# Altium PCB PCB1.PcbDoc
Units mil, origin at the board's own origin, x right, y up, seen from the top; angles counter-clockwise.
Board outline 6095 x 3360 mil, 2 copper layers (Top Layer, Bottom Layer); 128 components, 157 nets, 524 pads, 0 vias.
Unrouted connection lines stored in the file: 80.
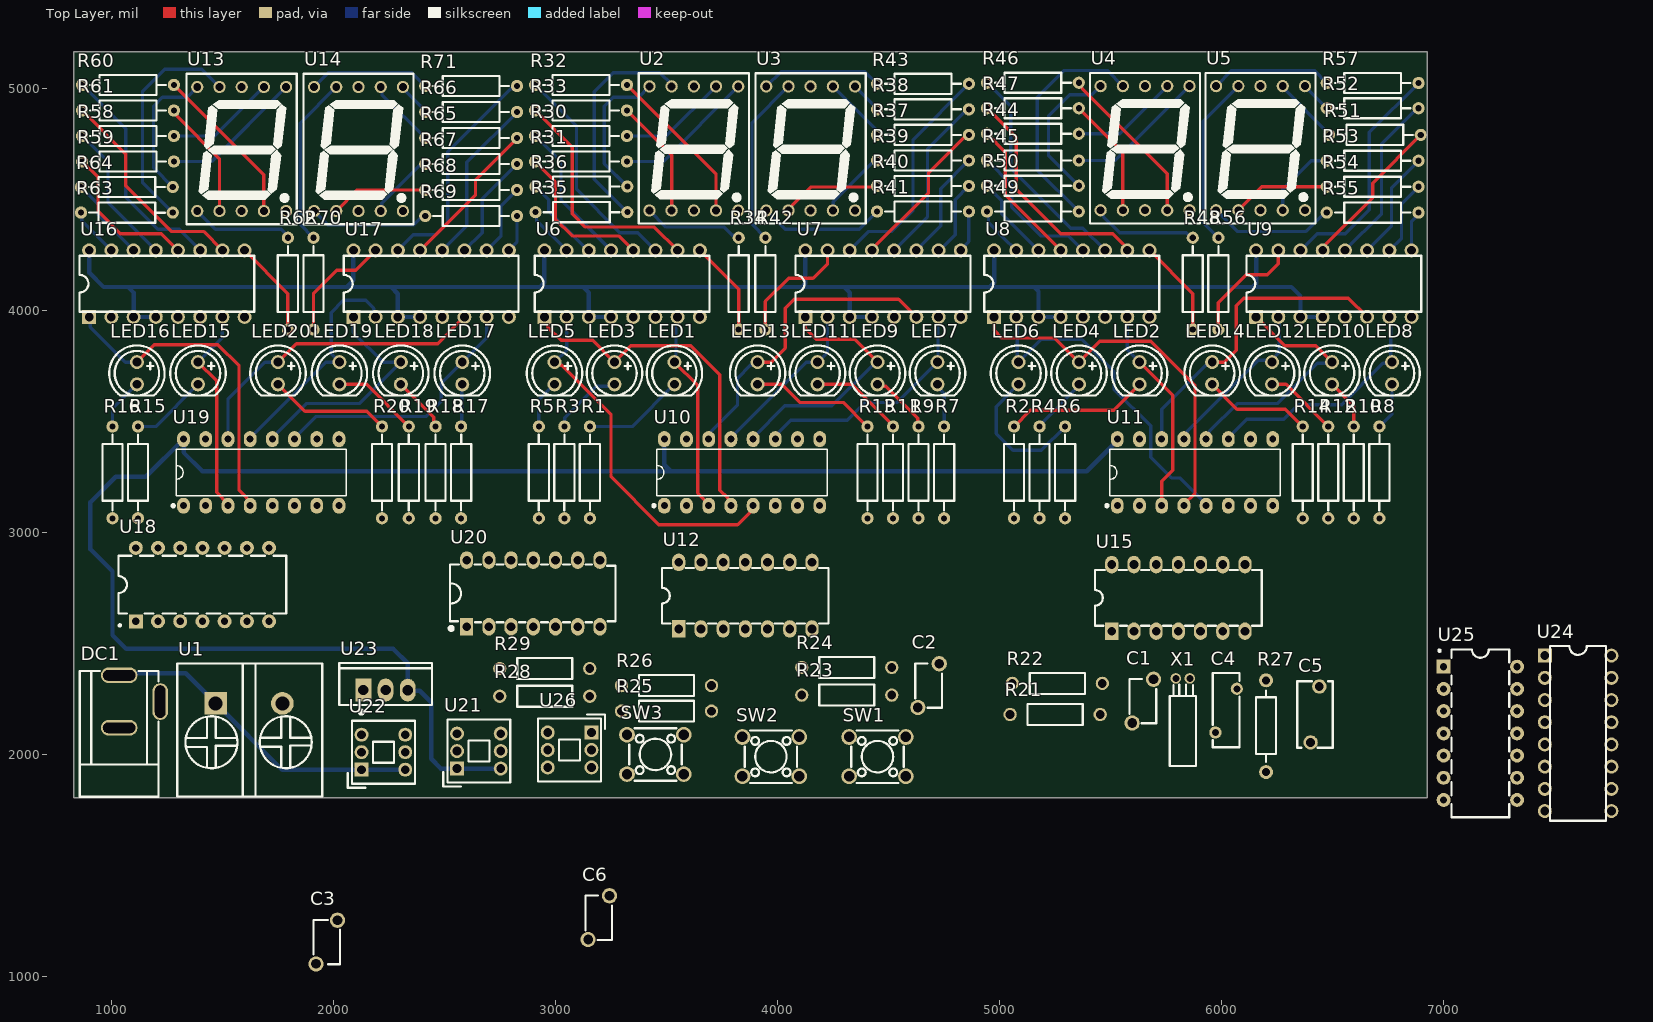
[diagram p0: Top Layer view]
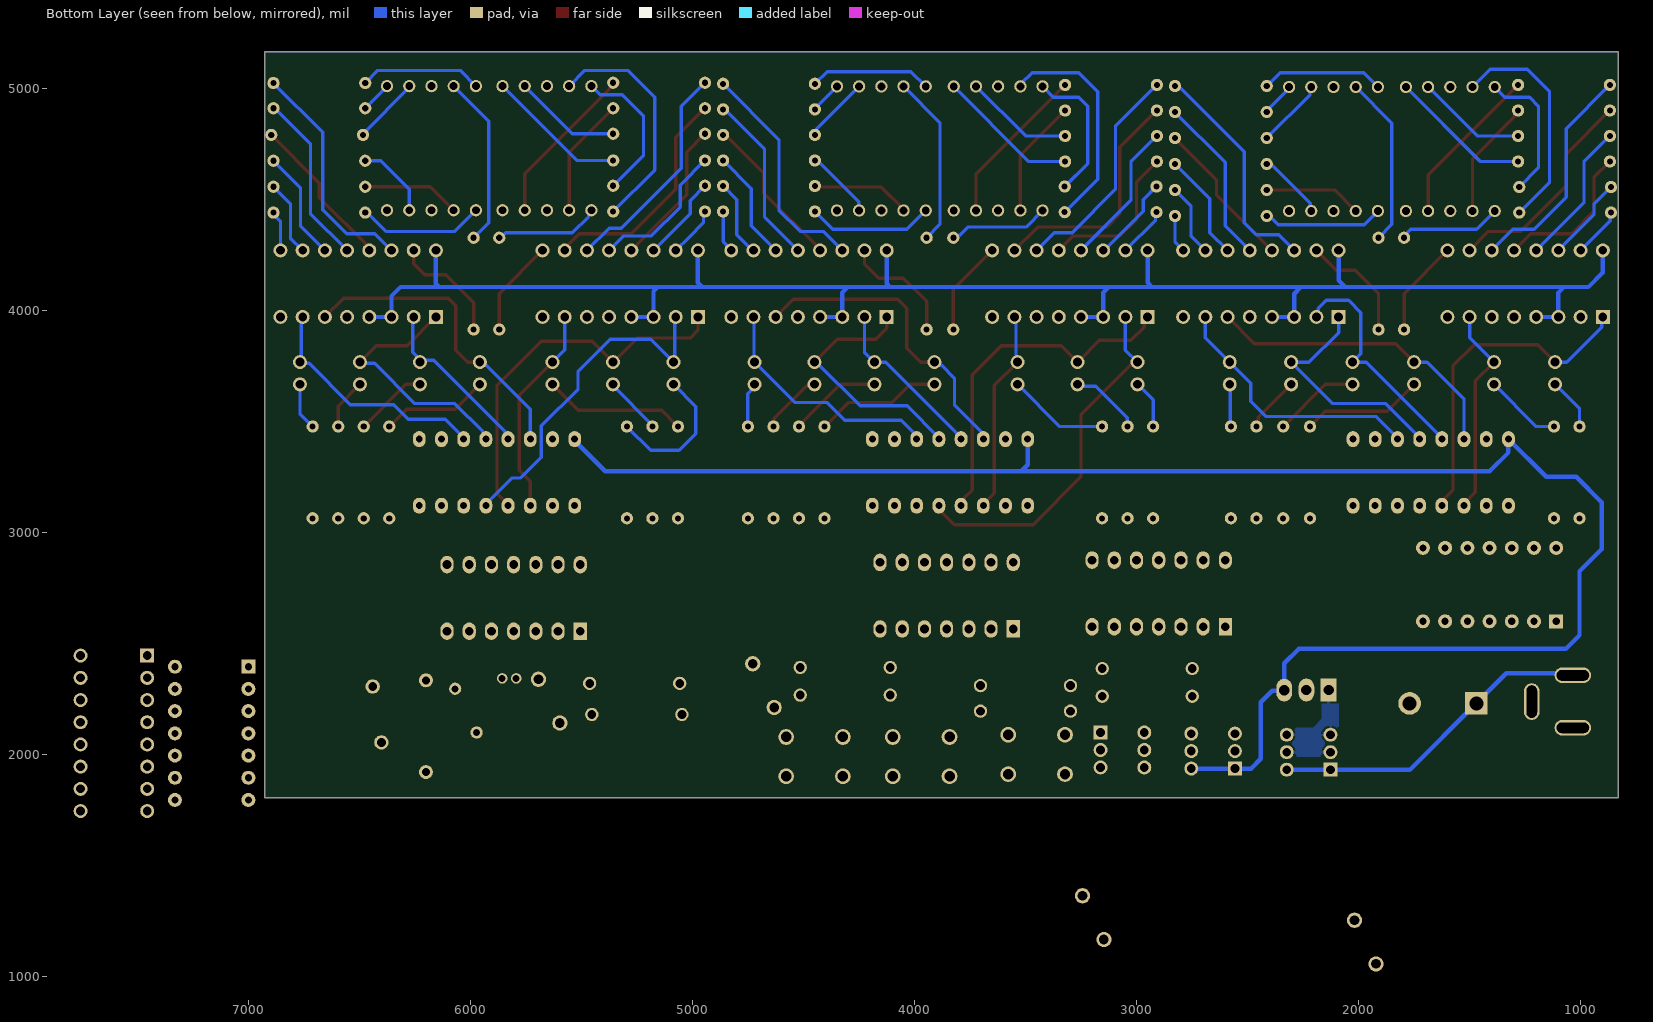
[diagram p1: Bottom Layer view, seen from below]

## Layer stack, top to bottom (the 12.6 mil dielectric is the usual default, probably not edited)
Top Solder: solder mask 0.4, Solder Resist, Dk 3.5
Top Layer: signal copper 1.4
Dielectric 1: dielectric 12.6, FR-4, Dk 4.8
Bottom Layer: signal copper 1.4
Bottom Solder: solder mask 0.4, Solder Resist, Dk 3.5

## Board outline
830,1805 6925,1805 6925,5165 830,5165

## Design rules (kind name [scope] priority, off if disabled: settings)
Clearance [All] p1: gap=10 ignorepadtopadclearanceinfootprint=FALSE
PolygonConnect [All] p1: connectstyle=Relief reliefconductorwidth=10 reliefentries=4 polygonreliefangle="90 Angle" airgapwidth=10
RoutingVias [All] p1: holewidth=28 width=50 viastyle="Through Hole" minholewidth=28 minwidth=50 maxholewidth=28 maxwidth=50
SolderMaskExpansion [All] p1: expansion=4 istentingtop=FALSE
SupplyNets "Schematic Supply Nets_3" [InNet('GND')] p1: voltage=0.000
SupplyNets "Schematic Supply Nets_1" [InNet('+D5V')] p2: voltage=0.000
SupplyNets "Schematic Supply Nets" [InNet('+5')] p3: voltage=0.000
Width [All] p1: maxlimit=50 minlimit=10 preferedwidth=15 minimp=50.000000 maximp=50.000000 favimp=50.000000
30 further rules are at their usual default settings.

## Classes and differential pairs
component class Display_SEC_MIN: LED1 LED2 LED3 LED4 LED5 LED6 LED7 LED8 LED9 LED10 LED11 LED12 LED13 LED14 R1 R2 R3 R4 R5 R6 R7 R8 R9 R10 R11 R12 R13 R14 R30 R31 R32 R33 R34 R35 R36 R37 R38 R39 R40 R41 R42 R43 R44 R45 R46 R47 R48 R49 R50 R51 R52 R53 R54 R55 R56 R57 U2 U3 U4 U5 U6 U7 U8 U9 U10 U11
component class Display_Hour: LED15 LED16 LED17 LED18 LED19 LED20 R15 R16 R17 R18 R19 R20 R58 R59 R60 R61 R62 R63 R64 R65 R66 R67 R68 R69 R70 R71 U12 U13 U14 U15 U16 U17 U18 U19 U20
component class CLK_SW: C1 C2 C3 C4 C5 C6 DC1 R21 R22 R23 R24 R25 R26 R27 R28 R29 SW1 SW2 SW3 U1 U21 U22 U23 U24 U25 U26 X1

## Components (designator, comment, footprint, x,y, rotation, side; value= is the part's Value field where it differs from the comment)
C1 "100pF" CAP-TH_L5.0-W3.0-P5.00-D0.6-S2.45 5645,2240 r90 top
C2 "100pF" CAP-TH_L5.0-W3.0-P5.00-D0.6-S2.45 4680,2310 r90 top
C3 "100pF" CAP-TH_L5.0-W3.0-P5.00-D0.6-S2.45 1970,1155 r270 top
C4 "560pF" CAP-TH_L8.5-W3.0-P5.00-D0.6-S2.5 6020,2197.19 r90 top
C5 "22pF" CAP-TH_L7.4-W4.0-P6.40-D0.5-S1.00 6420,2180 r90 top
C6 "100pF" CAP-TH_L5.0-W3.0-P5.00-D0.6-S2.45 3195,1265 r90 top
DC1 "DC-005-2.5A-2.0" CONN-TH_DC-005-2.5A-2.0 1127.53,2238.1 r90 top
LED1 "WP7113ID" LED-TH_BD5.0-P2.54-FD 3535.52,3716.7 r270 top locked
LED2 "WP7113ID" LED-TH_BD5.0-P2.54-FD 5630,3716.7 r270 top locked
LED3 "WP7113ID" LED-TH_BD5.0-P2.54-FD 3265.52,3716.7 r270 top locked
LED4 "WP7113ID" LED-TH_BD5.0-P2.54-FD 5357.5,3716.7 r270 top locked
LED5 "WP7113ID" LED-TH_BD5.0-P2.54-FD 2995.52,3716.7 r270 top locked
LED6 "WP7113ID" LED-TH_BD5.0-P2.54-FD 5085,3716.7 r270 top locked
LED7 "WP7113ID" LED-TH_BD5.0-P2.54-FD 4720.21,3716.7 r270 top locked
LED8 "WP7113ID" LED-TH_BD5.0-P2.54-FD 6767.15,3716.7 r270 top locked
LED9 "WP7113ID" LED-TH_BD5.0-P2.54-FD 4450.21,3716.7 r270 top locked
LED10 "WP7113ID" LED-TH_BD5.0-P2.54-FD 6497.15,3716.7 r270 top locked
LED11 "WP7113ID" LED-TH_BD5.0-P2.54-FD 4180.21,3716.7 r270 top locked
LED12 "WP7113ID" LED-TH_BD5.0-P2.54-FD 6227.15,3716.7 r270 top locked
LED13 "WP7113ID" LED-TH_BD5.0-P2.54-FD 3910.21,3716.7 r270 top locked
LED14 "WP7113ID" LED-TH_BD5.0-P2.54-FD 5957.15,3716.7 r270 top locked
LED15 "WP7113ID" LED-TH_BD5.0-P2.54-FD 1390,3716.7 r270 top locked
LED16 "WP7113ID" LED-TH_BD5.0-P2.54-FD 1115,3716.7 r270 top locked
LED17 "WP7113ID" LED-TH_BD5.0-P2.54-FD 2580.21,3716.7 r270 top locked
LED18 "WP7113ID" LED-TH_BD5.0-P2.54-FD 2303.55,3716.7 r270 top locked
LED19 "WP7113ID" LED-TH_BD5.0-P2.54-FD 2026.88,3716.7 r270 top locked
LED20 "WP7113ID" LED-TH_BD5.0-P2.54-FD 1750.21,3716.7 r270 top locked
R1 "330Ω" RES-TH_BD2.3-L6.5-P10.50-D0.5 3155,3270 r270 top locked
R2 "330Ω" RES-TH_BD2.3-L6.5-P10.50-D0.5 5065,3270 r270 top locked
R3 "330Ω" RES-TH_BD2.3-L6.5-P10.50-D0.5 3040,3270 r270 top locked
R4 "330Ω" RES-TH_BD2.3-L6.5-P10.50-D0.5 5180,3270 r270 top locked
R5 "330Ω" RES-TH_BD2.3-L6.5-P10.50-D0.5 2925,3270 r270 top locked
R6 "330Ω" RES-TH_BD2.3-L6.5-P10.50-D0.5 5295,3270 r270 top locked
R7 "330Ω" RES-TH_BD2.3-L6.5-P10.50-D0.5 4750,3270 r90 top locked
R8 "330Ω" RES-TH_BD2.3-L6.5-P10.50-D0.5 6710,3270 r90 top locked
R9 "330Ω" RES-TH_BD2.3-L6.5-P10.50-D0.5 4635,3270 r90 top locked
R10 "330Ω" RES-TH_BD2.3-L6.5-P10.50-D0.5 6595,3270 r90 top locked
R11 "330Ω" RES-TH_BD2.3-L6.5-P10.50-D0.5 4520,3270 r90 top locked
R12 "330Ω" RES-TH_BD2.3-L6.5-P10.50-D0.5 6480,3270 r90 top locked
R13 "330Ω" RES-TH_BD2.3-L6.5-P10.50-D0.5 4405,3270 r90 top locked
R14 "330Ω" RES-TH_BD2.3-L6.5-P10.50-D0.5 6365,3270 r90 top locked
R15 "330Ω" RES-TH_BD2.3-L6.5-P10.50-D0.5 1120,3270 r270 top locked
R16 "330Ω" RES-TH_BD2.3-L6.5-P10.50-D0.5 1005,3270 r270 top locked
R17 "330Ω" RES-TH_BD2.3-L6.5-P10.50-D0.5 2575,3270 r90 top locked
R18 "330Ω" RES-TH_BD2.3-L6.5-P10.50-D0.5 2460.04,3270 r90 top locked
R19 "330Ω" RES-TH_BD2.3-L6.5-P10.50-D0.5 2339.48,3270 r90 top locked
R20 "330Ω" RES-TH_BD2.3-L6.5-P10.50-D0.5 2218.93,3270 r90 top locked
R21 "10kΩ" RES-TH_BD2.4-L6.3-P10.30-D0.6 5250,2180 r180 top
R22 "10kΩ" RES-TH_BD2.4-L6.3-P10.30-D0.6 5260,2320 r180 top
R23 "10kΩ" RES-TH_BD2.4-L6.3-P10.30-D0.6 4311.76,2267.24 r180 top
R24 "10kΩ" RES-TH_BD2.4-L6.3-P10.30-D0.6 4311.76,2391.73 r180 top
R25 "10kΩ" RES-TH_BD2.4-L6.3-P10.30-D0.6 3500,2195 r0 top
R26 "10kΩ" RES-TH_BD2.4-L6.3-P10.30-D0.6 3500,2310 r180 top
R27 "10MΩ" RES-TH_BD2.2-L6.5-P10.50-D0.6 6200,2127.19 r90 top
R28 "10kΩ" RES-TH_BD2.4-L6.3-P10.30-D0.6 2951.76,2262.24 r180 top
R29 "10kΩ" RES-TH_BD2.4-L6.3-P10.30-D0.6 2951.76,2386.73 r0 top
R30 "330Ω" RES-TH_BD2.3-L6.5-P10.50-D0.5 3115,4785 r0 top locked
R31 "330Ω" RES-TH_BD2.3-L6.5-P10.50-D0.5 3115,4670 r0 top locked
R32 "330Ω" RES-TH_BD2.3-L6.5-P10.50-D0.5 3115,5015 r0 top locked
R33 "330Ω" RES-TH_BD2.3-L6.5-P10.50-D0.5 3115,4900 r0 top locked
R34 "330Ω" RES-TH_BD2.3-L6.5-P10.50-D0.5 3825,4120 r90 top locked
R35 "330Ω" RES-TH_BD2.3-L6.5-P10.50-D0.5 3116.75,4441.96 r0 top locked
R36 "330Ω" RES-TH_BD2.3-L6.5-P10.50-D0.5 3116.75,4557.57 r0 top locked
R37 "330Ω" RES-TH_BD2.3-L6.5-P10.50-D0.5 4655,4790 r180 top locked
R38 "330Ω" RES-TH_BD2.3-L6.5-P10.50-D0.5 4655,4905 r180 top locked
R39 "330Ω" RES-TH_BD2.3-L6.5-P10.50-D0.5 4655,4675 r180 top locked
R40 "330Ω" RES-TH_BD2.3-L6.5-P10.50-D0.5 4655,4560 r180 top locked
R41 "330Ω" RES-TH_BD2.3-L6.5-P10.50-D0.5 4655,4445 r180 top locked
R42 "330Ω" RES-TH_BD2.3-L6.5-P10.50-D0.5 3945,4120 r90 top locked
R43 "330Ω" RES-TH_BD2.3-L6.5-P10.50-D0.5 4655,5020 r180 top locked
R44 "330Ω" RES-TH_BD2.3-L6.5-P10.50-D0.5 5150,4795 r0 top locked
R45 "330Ω" RES-TH_BD2.3-L6.5-P10.50-D0.5 5150,4675 r0 top locked
R46 "330Ω" RES-TH_BD2.3-L6.5-P10.50-D0.5 5150,5025 r0 top locked
R47 "330Ω" RES-TH_BD2.3-L6.5-P10.50-D0.5 5150,4910 r0 top locked
R48 "330Ω" RES-TH_BD2.3-L6.5-P10.50-D0.5 5870,4120 r90 top locked
R49 "330Ω" RES-TH_BD2.3-L6.5-P10.50-D0.5 5150,4445 r0 top locked
R50 "330Ω" RES-TH_BD2.3-L6.5-P10.50-D0.5 5150,4560.83 r0 top locked
R51 "330Ω" RES-TH_BD2.3-L6.5-P10.50-D0.5 6690,4790 r180 top locked
R52 "330Ω" RES-TH_BD2.3-L6.5-P10.50-D0.5 6680,4910 r180 top locked
R53 "330Ω" RES-TH_BD2.3-L6.5-P10.50-D0.5 6680,4673.33 r180 top locked
R54 "330Ω" RES-TH_BD2.3-L6.5-P10.50-D0.5 6680,4556.67 r180 top locked
R55 "330Ω" RES-TH_BD2.3-L6.5-P10.50-D0.5 6680,4440 r180 top locked
R56 "330Ω" RES-TH_BD2.3-L6.5-P10.50-D0.5 5985,4120 r90 top locked
R57 "330Ω" RES-TH_BD2.3-L6.5-P10.50-D0.5 6680,5023.33 r180 top locked
R58 "330Ω" RES-TH_BD2.3-L6.5-P10.50-D0.5 1075,4785 r0 top locked
R59 "330Ω" RES-TH_BD2.3-L6.5-P10.50-D0.5 1075,4670 r0 top locked
R60 "330Ω" RES-TH_BD2.3-L6.5-P10.50-D0.5 1075,5015 r0 top locked
R61 "330Ω" RES-TH_BD2.3-L6.5-P10.50-D0.5 1075,4900 r0 top locked
R62 "330Ω" RES-TH_BD2.3-L6.5-P10.50-D0.5 1795,4120 r90 top locked
R63 "330Ω" RES-TH_BD2.3-L6.5-P10.50-D0.5 1070,4440 r0 top locked
R64 "330Ω" RES-TH_BD2.3-L6.5-P10.50-D0.5 1070,4555 r0 top locked
R65 "330Ω" RES-TH_BD2.3-L6.5-P10.50-D0.5 2620,4776 r180 top locked
R66 "330Ω" RES-TH_BD2.3-L6.5-P10.50-D0.5 2620,4893 r180 top locked
R67 "330Ω" RES-TH_BD2.3-L6.5-P10.50-D0.5 2620,4659 r180 top locked
R68 "330Ω" RES-TH_BD2.3-L6.5-P10.50-D0.5 2620,4542 r180 top locked
R69 "330Ω" RES-TH_BD2.3-L6.5-P10.50-D0.5 2620,4425 r180 top locked
R70 "330Ω" RES-TH_BD2.3-L6.5-P10.50-D0.5 1910,4120 r90 top locked
R71 "330Ω" RES-TH_BD2.3-L6.5-P10.50-D0.5 2620,5010 r180 top locked
SW1 "TS665CJ" SW-TH_4P-L6.0-W6.0-P4.50-LS6.5 4450,1990 r180 top
SW2 "TS665CJ" SW-TH_4P-L6.0-W6.0-P4.50-LS6.5 3970,1990 r180 top
SW3 "TS665CJ" SW-TH_4P-L6.0-W6.0-P4.50-LS6.5 3450,2000 r0 top
U1 "DBT50G-7.62-2P" CONN-TH_2P-P7.62_L15.2-W16.7-EX4.2 1620,2230 r0 top
U2 "HDSP-5501" LED-SEG-TH_HDSP-A 3623.03,4729.02 r0 top locked
U3 "HDSP-5501" LED-SEG-TH_HDSP-A 4149.09,4729.02 r0 top locked
U4 "HDSP-5501" LED-SEG-TH_HDSP-A 5655,4730 r0 top locked
U5 "HDSP-5501" LED-SEG-TH_HDSP-A 6175,4730 r0 top locked
U6 "CD4511BE" DIP-16_L19.8-W6.5-P2.54-LS7.6-BL 3300,4120 r0 top locked
U7 "CD4511BE" DIP-16_L19.8-W6.5-P2.54-LS7.6-BL 4475.01,4120 r0 top locked
U8 "CD4511BE" DIP-16_L19.8-W6.5-P2.54-LS7.6-BL 5325.01,4120 r0 top locked
U9 "CD4511BE" DIP-16_L19.8-W6.5-P2.54-LS7.6-BL 6505.01,4120 r0 top locked
U10 "CD4518BE" DIP-16_L19.3-W6.4-P2.54-LS7.6-BL 3840,3270 r0 top locked
U11 "CD4518BE" DIP-16_L19.3-W6.4-P2.54-LS7.6-BL 5880,3270 r0 top locked
U12 "CD4081BE" PDIP-14_L19.3-W6.4-P2.54-LS7.6-BL 3855,2715 r0 top
U13 "HDSP-5501" LED-SEG-TH_HDSP-A 1586.86,4726.42 r0 top locked
U14 "HDSP-5501" LED-SEG-TH_HDSP-A 2112.92,4726.42 r0 top locked
U15 "CD4081BE" PDIP-14_L19.3-W6.4-P2.54-LS7.6-BL 5805,2705 r0 top
U16 "CD4511BE" DIP-16_L19.8-W6.5-P2.54-LS7.6-BL 1250.01,4120 r0 top locked
U17 "CD4511BE" DIP-16_L19.8-W6.5-P2.54-LS7.6-BL 2440,4120 r0 top locked
U18 "CD4071BE" DIP-14_L19.2-W6.6-P2.54-LS10.9-BL 1410,2765 r0 top
U19 "CD4518BE" DIP-16_L19.3-W6.4-P2.54-LS7.6-BL 1675,3270 r0 top locked
U20 "CD40106BD" DIP-14_L19.1-W6.4-P2.54-LS7.6-BL 2900,2725 r0 top
U21 "PS-7054DVB-6PL" SW-TH_6P-L7.0-W7.0-P2.00 2655,2015 r180 top
U22 "PS-7054DVB-6PL" SW-TH_6P-L7.0-W7.0-P2.00 2225,2010 r180 top
U23 "L7805CV-DG" TO-220-3_L10.0-W4.5-P2.54-L 2235,2290 r0 top
U24 "CD4060BE" DIP-16_L19.8-W6.5-P2.54-LS7.6-BL 7605,2095 r270 top
U25 "CD4013BE" DIP-14_L19.2-W6.6-P2.54-LS10.9-BL 7165,2095 r270 top
U26 "PS-7054DVB-6PL" SW-TH_6P-L7.0-W7.0-P2.00 3063.43,2020 r0 top
X1 "32.768kHz" OSC-TH_BD3.1-P0.8-D0.3 5825,2342.19 r90 top

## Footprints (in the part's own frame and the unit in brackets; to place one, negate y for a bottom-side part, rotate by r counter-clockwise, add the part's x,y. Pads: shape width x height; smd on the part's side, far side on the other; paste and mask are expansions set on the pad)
CAP-TH_L5.0-W3.0-P5.00-D0.6-S2.45 [mm]
  round 1.75 hole 1.1 paste-2539.97 mask+0.05: 1(-2.5,1.225) 2(2.5,-1.225)
  silkscreen extent -2.54,-1.52 2.54,1.52
CAP-TH_L7.4-W4.0-P6.40-D0.5-S1.00 [mm]
  round 1.65 hole 1 copper offset 0,0 paste-2539.97 mask+0.05: 1(-3.2,0.5) 2(3.2,-0.5)
  silkscreen extent -3.81,-2.03 3.81,2.03
CAP-TH_L8.5-W3.0-P5.00-D0.6-S2.5 [mm]
  round 1.4 hole 0.8: 1(-2.5,1.225) 2(2.5,-1.225)
  silkscreen extent -4.19,-1.52 4.32,1.52
CONN-TH_2P-P7.62_L15.2-W16.7-EX4.2 [mm]
  rect 2.6x2.6 hole 1.6 paste-2539.97 mask+0.051: 1(-3.81,0)
  round 2.6 hole 1.6 paste-2539.97 mask+0.051: 2(3.81,0)
  silkscreen extent -8.22,-10.65 8.38,4.55
CONN-TH_DC-005-2.5A-2.0 [mm]
  oval 1.8x4.2 hole 1.2 slot 3.7 at 90 deg paste-2539.97 mask+0.051: 1(3,2.35) 2(-3,2.35)
  oval 4.2x1.8 hole 1.2 slot 3.7 at 0 deg paste-2539.97 mask+0.051: 3(0,-2.35)
  silkscreen extent -10.9,-2.15 3.5,6.85
DIP-14_L19.1-W6.4-P2.54-LS7.6-BL [mm]
  rect 1.5x2 hole 1: 1(-7.62,-3.81)
  oval 1.5x2 hole 1: 2(-5.08,-3.81) 3(-2.54,-3.81) 4(0,-3.81) 5(2.54,-3.81) 6(5.08,-3.81) 7(7.62,-3.81) 8(7.62,3.81) 9(5.08,3.81) 10(2.54,3.81) 11(0,3.81) 12(-2.54,3.81) 13(-5.08,3.81) 14(-7.62,3.81)
  silkscreen extent -9.59,-4.2 9.4,3.3
DIP-14_L19.2-W6.6-P2.54-LS10.9-BL [mil]
  rect 63x63 hole 32: 1(-300,-165.35)
  round 63 hole 32: 2(-200,-165.35) 3(-100,-165.35) 4(0,-165.35) 5(100,-165.35) 6(200,-165.35) 7(300,-165.35) 8(300,165.35) 9(200,165.35) 10(100,165.35) 11(0,165.35) 12(-100,165.35) 13(-200,165.35) 14(-300,165.35)
  silkscreen extent -378,-189 378,130
DIP-16_L19.3-W6.4-P2.54-LS7.6-BL [mm]
  oval 1.46x1.825 hole 0.8: 1(-8.89,-3.81) 2(-6.35,-3.81) 3(-3.81,-3.81) 4(-1.27,-3.81) 5(1.27,-3.81) 6(3.81,-3.81) 7(6.35,-3.81) 8(8.89,-3.81) 9(8.89,3.81) 10(6.35,3.81) 11(3.81,3.81) 12(1.27,3.81) 13(-1.27,3.81) 14(-3.81,3.81) 15(-6.35,3.81) 16(-8.89,3.81)
  silkscreen extent -10.22,-3.96 9.73,2.67
DIP-16_L19.8-W6.5-P2.54-LS7.6-BL [mm]
  rect 1.6x1.6 hole 1: 1(-8.89,-3.81)
  round 1.6 hole 1 copper offset 0,0: 2(-6.35,-3.81) 3(-3.81,-3.81) 4(-1.27,-3.81) 5(1.27,-3.81) 6(3.81,-3.81) 7(6.35,-3.81) 8(8.89,-3.81) 9(8.89,3.81) 10(6.35,3.81) 11(3.81,3.81) 12(1.27,3.81) 13(-1.27,3.81) 14(-3.81,3.81) 15(-6.35,3.81) 16(-8.89,3.81)
  silkscreen extent -10,-3.2 10,3.2
LED-SEG-TH_HDSP-A [mil]
  round 55.12 hole 35.43: 1(-200,-279.5) 2(-100,-279.5) 3(0,-279.5) 4(100,-279.5) 5(200,-279.5) 6(200,279.5) 7(100,279.5) 8(0,279.5) 9(-100,279.5) 10(-200,279.5)
  silkscreen extent -248,-339 248,339
LED-TH_BD5.0-P2.54-FD [mm]
  round 1.6 hole 1: 1(-1.27,0) 2(1.27,0)
  silkscreen extent -3.17,-3.17 2.54,3.17
OSC-TH_BD3.1-P0.8-D0.3 [mm]
  round 1.2 hole 0.8: 1(0,0.8) 2(0,-0.8)
  silkscreen extent -10,-1.5 -0.7,1.5
PDIP-14_L19.3-W6.4-P2.54-LS7.6-BL [mm]
  rect 1.5x2 hole 1: 1(-7.62,-3.81)
  oval 1.5x2 hole 1: 2(-5.08,-3.81) 3(-2.54,-3.81) 4(0,-3.81) 5(2.54,-3.81) 6(5.08,-3.81) 7(7.62,-3.81) 8(7.62,3.81) 9(5.08,3.81) 10(2.54,3.81) 11(0,3.81) 12(-2.54,3.81) 13(-5.08,3.81) 14(-7.62,3.81)
  silkscreen extent -9.53,-3.17 9.53,3.17
RES-TH_BD2.2-L6.5-P10.50-D0.6 [mm]
  round 1.6 hole 0.914: 1(-5.25,0) 2(5.25,0)
  silkscreen extent -4.06,-1.14 4.06,1.14
RES-TH_BD2.3-L6.5-P10.50-D0.5 [mm]
  round 1.4 hole 0.7: 1(-5.25,0) 2(5.25,0)
  silkscreen extent -4.32,-1.15 4.32,1.15
RES-TH_BD2.4-L6.3-P10.30-D0.6 [mil]
  round 60 hole 39.37: 1(-202.76,0) 2(202.76,0)
  silkscreen extent -124,-47 124,47
SW-TH_4P-L6.0-W6.0-P4.50-LS6.5 [mm]
  round 1.8 hole 1.2: 1(-3.25,2.25) 2(3.25,2.25) 3(-3.25,-2.25) 4(3.25,-2.25)
  silkscreen extent -3,-3 3,3
SW-TH_6P-L7.0-W7.0-P2.00 [mm]
  rect 1.6x1.6 hole 1: 1(2.5,2)
  round 1.6 hole 1: 2(2.5,0) 3(2.5,-2) 4(-2.5,2) 5(-2.5,0) 6(-2.5,-2)
  silkscreen extent -3.6,-3.6 4.06,4.06
TO-220-3_L10.0-W4.5-P2.54-L [mm]
  rect 1.8x2.6 hole 1.2: 1(-2.54,0.005)
  oval 1.8x2.6 hole 1.2: 2(0,0.005)
  oval 1.8x2.6 hole 1.2 copper offset 0,0: 3(2.54,-0.005)
  silkscreen extent -5.3,-2.73 5.3,3.09

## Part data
C1 C2 C3 C6: library part Cap_100pF_50V_ceramic, JLCPCB Part Class="Extended Part", LCSC Part Name="100pF ±10% 50V", Manufacturer=SHM(南方宏明), Manufacturer Part=DCT101K20Y5PF6FJ5A0, Temperature Coefficient=Y5P, Tolerance=±10%, Voltage Rating=50V
C4: library part Cap_560pF_50V_ceraic, JLCPCB Part Class="Extended Part", LCSC Part Name="560pF ±5% 50V", Manufacturer=SHM(南方宏明), Manufacturer Part="DCC561J34SL F6FJ5A0", Temperature Coefficient=SL, Tolerance=±5%, Voltage Rating=50V
C5: library part Cap_22pF_50V_ceramic, JLCPCB Part Class="Extended Part", LCSC Part Name="22pF ±10% 50V", Manufacturer=Dersonic(德尔创), Manufacturer Part=CC1H220KA1EDCH4B1100, Temperature Coefficient=NP0, Tolerance=±10%, Voltage Rating=50V
DC1: JLCPCB Part Class="Extended Part", Manufacturer="XKB Connection(中国星坤)"
LED1 LED2 LED3 LED4 LED5 LED6 LED7 LED8 LED9 LED10 LED11 LED12 LED13 LED14 LED15 LED16 LED17 LED18 LED19 LED20: library part D_LED_2mm_red, Emitted Color=Red, Forward Current=20mA, Forward Voltage (VF)=2V, JLCPCB Part Class="Extended Part", Lens Color="Red Lens", Manufacturer=Kingbright
R1 R2 R3 R4 R5 R6 R7 R8 R9 R10 R11 R12 R13 R14 R15 R16 R17 R18 R19 R20 R30 R31 R32 R33 R34 R35 R36 R37 R38 R39 R40 R41 R42 R43 R44 R45 R46 R47 R48 R49 R50 R51 R52 R53 R54 R55 R56 R57 R58 R59 R60 R61 R62 R63 R64 R65 R66 R67 R68 R69 R70 R71: library part Reg_330R_0.25W, JLCPCB Part Class="Extended Part", LCSC Part Name="330Ω ±1% 250mW 金属膜电阻", Manufacturer=CCO(千志电子), Manufacturer Part="MF1/4W-330Ω±1% T", Operating Temperature=-55℃~+155℃, Power(Watts)=250mW, Temperature Coefficient=±100ppm/℃, Tolerance=±1%, Voltage-Supply(Max)=250V
R21 R22 R23 R24 R25 R26 R28 R29: library part Reg_10k_0.25W, JLCPCB Part Class="Extended Part", LCSC Part Name="10kΩ ±1% 250mW 金属膜电阻", Manufacturer=Tyohm(幸亚电阻), Manufacturer Part=RN1/4W10KFT/BA1, Operating Temperature Range=-55℃~+125℃, Overload Voltage (Max)=250V, Power(Watts)=250mW, Temperature Coefficient=±50ppm/℃, Tolerance=±1%
R27: library part Reg_10M_0.25W, JLCPCB Part Class="Extended Part", LCSC Part Name="10MΩ ±5% 250mW 碳膜电阻", Manufacturer=CCO(千志电子), Manufacturer Part="CF1/4W-10MΩ±5% T", Operating Temperature=-55℃~+155℃, Power(Watts)=250mW, Temperature Coefficient=-1500ppm/℃~0ppm/℃, Tolerance=±5%, Voltage-Supply(Max)=250V
SW1 SW2 SW3: Contact Current=50mA, JLCPCB Part Class="Extended Part", LCSC Part Name="6*6*5mm 直插 轻触开关", Manufacturer="SHOU HAN(首韩)", Voltage Rating (DC)=12V
U1: JLCPCB Part Class="Extended Part", Manufacturer=DORABO(地博电气), Manufacturer Part=DBT50G-7.62-2P-BK-P
U2 U3 U4 U5 U13 U14: JLCPCB Part Class="Extended Part", Manufacturer=Broadcom/AVAGO(安华高)
U6 U7 U8 U9 U16 U17: library part CD4511BE_C507153, JLCPCB Part Class="Extended Part", LCSC Part Name="CMOS BCD 到 7 段 LED 锁存解码器驱动器", Manufacturer=HGSEMI(华冠)
U10 U11 U19: JLCPCB Part Class="Extended Part", Manufacturer=TI(德州仪器), Operating Temperature=-55℃~+125℃, Voltage - Supply=3V~18V
U12 U15 U18: Current - Output High(IOH)=3.4mA, JLCPCB Part Class="Extended Part", Manufacturer=TI(德州仪器), Operating Temperature=-55℃~+125℃, Quiescent Current=1uA, Voltage - Supply=3V~18V
U20: JLCPCB Part Class="Extended Part", Manufacturer=Sungine(双竞集成), Voltage - Supply=3V~15V
U21 U22 U26: JLCPCB Part Class="Extended Part", LCSC Part Name=7*7自锁按键开关, Manufacturer=G-Switch(品赞), Operating Force=250gf
U23: Dropout Voltage=2V@(1A), JLCPCB Part Class="Extended Part", LCSC Part Name=正稳压器IC, Manufacturer=ST(意法半导体), Maximum Input Voltage=35V, Operating Temperature=0℃~+125℃, Output Current=1.5A, Output Voltage=5V, Power Supply Rejection Ratio (PSRR)=62dB@(120Hz), standby current=8mA
U24: JLCPCB Part Class="Extended Part", LCSC Part Name="CMOS 14 级纹波进位二进制计数器/除法器和振荡器", Manufacturer=HGSEMI(华冠)
U25: Clock Frequency=24MHz, Current - Output High(IOH)=6.8mA, Input Capacitance=5pF, JLCPCB Part Class="Extended Part", Manufacturer=TI(德州仪器), Operating Temperature=-55℃~+125℃, Quiescent Current=4uA, Voltage - Supply=3V~18V
X1: library part AB38T-32.768KHZ, Equivalent Series Resistance (ESR)=30kΩ, Frequency Stability(Full temperature range)=-, JLCPCB Part Class="Extended Part", LCSC Part Name="32.768kHz ±20ppm 12.5pF", Manufacturer=ABRACON, Normal temperature Frequency Tolerance=±20ppm

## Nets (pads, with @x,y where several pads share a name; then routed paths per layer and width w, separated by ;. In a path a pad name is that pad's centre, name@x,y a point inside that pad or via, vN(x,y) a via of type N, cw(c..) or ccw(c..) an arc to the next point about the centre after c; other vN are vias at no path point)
1H1: LED17.1 U12.1 U17.7 U19.11 | length 1199.6
  Bottom Layer w15: U19.11 1825,3427.18 1919.56,3521.75 2416.75,3521.75 2485,3590 2485,3671.49 LED17.1 2690,3876.49 U17.7
1H2: LED18.1 U17.1 U19.12 | length 1065.1
  Bottom Layer w15: U19.12 1725,3427.18 1877.82,3580 2116.84,3580 LED18.1 2223.3,3766.7 2090,3900 U17.1
1H3: LED19.1 U12.5 U17.2 U19.13 | length 1059.7
  Bottom Layer w15: U19.13 1625,3427.18 1964.52,3766.7 LED19.1 1990,3803.58 1990,3990 2045,4045 2145,4045 2181.82,4008.18 2181.82,3978.17 U17.2
1H4: LED20.1 U12.2 U17.6 U19.14 | length 1398.3
  Top Layer w15: LED20.1 1833.51,3850 2470,3850 U17.6
  Bottom Layer w15: U19.14 1525,3600 1691.7,3766.7 LED20.1
1H_CLK: U10.7 U12.11 U19.9
1H_EN: U19.10
1M1: LED7.1 U7.7 U10.11 U12.8 | length 1087.9
  Bottom Layer w15: U10.11 3990,3435 4060,3505 4315,3505 4395,3585 4538.5,3585 LED7.1 4722.61,3769.11 4722.61,3967.62 U7.7
1M2: LED9.1 U7.1 U10.12 | length 1146.7
  Top Layer w15: U7.1 4125.01,3919.99 4175,3870 4346.91,3870 LED9.1
  Bottom Layer w15: U10.12 3890,3427.18 4032.82,3570 4245,3570 4441.7,3766.7 LED9.1
1M3: LED11.1 U7.2 U10.13 | length 759.9
  Bottom Layer w15: U10.13 3790,3427.18 4129.52,3766.7 LED11.1 4225.01,3811.51 U7.2
1M4: LED13.1 U7.6 U10.14 U12.9 | length 1419.5
  Top Layer w15: LED13.1 3971.7,3766.7 4035,3830 4035,4010 4075,4050 4545.01,4050 U7.6
  Bottom Layer w15: U10.14 3698.13,3428.13 3698.13,3453.13 3820,3575 3820,3695 3877.77,3752.77 3883.29,3752.77 3897.22,3766.7 LED13.1
1M_CLK: U10.9 U11.7 U15.11
1M_EN: U10.10 U18.11
1S1: LED8.1 U9.7 U11.11 U15.8 | length 1093.3
  Bottom Layer w15: U11.11 6030,3427.18 6112.81,3510 6280,3510 6345,3575 6540,3575 6726.25,3761.25 6761.69,3761.25 LED8.1 6761.08,3772.77 6761.08,3963.93 U9.7
1S2: LED10.1 U9.1 U11.12 | length 1148.8
  Top Layer w15: U9.1 6285.01,3840 6423.85,3840 LED10.1
  Bottom Layer w15: U11.12 5930,3438.68 5944.82,3453.5 5944.82,3454.82 6070,3580 6250,3580 6431.25,3761.25 6491.69,3761.25 LED10.1
1S3: LED12.1 U9.2 U11.13 | length 778.3
  Bottom Layer w15: U11.13 5830,3438.68 5844.82,3453.5 5844.82,3454.82 6165,3775 6218.85,3775 LED12.1 6227.15,3777.37 6260,3810.22 6260,3965.01 U9.2
1S4: LED14.1 U9.6 U11.14 U15.9 | length 1419.5
  Top Layer w15: LED14.1 6011.7,3766.7 6065,3820 6065,4020 6100,4055 6570.01,4055 U9.6
  Bottom Layer w15: U11.14 5730,3555 5926.25,3751.25 5928.71,3751.25 5944.16,3766.7 LED14.1
1S_CLK: U11.9 U15.3
1S_EN: U11.10 U18.3
10H1: LED15.1 U16.7 U19.3 | length 951.5
  Top Layer w15: LED15.1 1475,3681.7 1475,3180 1525,3130 U19.3
  Bottom Layer w15: LED15.1 1500.01,3876.72 U16.7
10H2: LED16.1 U12.6 U16.1 U19.4 | length 1505.1
  Top Layer w15: LED16.1 1193.3,3845 1480,3845 1575,3750 1575,3190 1610.18,3154.82 1610.18,3153.5 1625,3138.68 U19.4
  Bottom Layer w15: U16.1 905.21,3964.8 905.21,3924.79 1063.3,3766.7 LED16.1
10H_EN: U12.3 U19.2
10M1: LED1.1 U6.7 U10.3 | length 920
  Top Layer w15: LED1.1 3640,3662.22 3640,3177.18 3690,3127.18 U10.3
  Bottom Layer w15: LED1.1 3542.76,3773.95 3542.76,3962.78 U6.7
10M2: LED3.1 U6.1 U10.4 U12.12 | length 1586.7
  Top Layer w15: U6.1 2965.21,3954.79 2965.21,3924.79 3025,3865 3167.22,3865 LED3.1 3338.81,3840 3610,3840 3740,3710 3740,3190 3775.18,3154.82 3775.18,3153.5 3790,3138.68 U10.4
10M3: LED5.1 U6.2 U10.5 U12.13 | length 1631.5
  Top Layer w15: LED5.1 3008.5,3766.7 3022.79,3752.41 3027.59,3752.41 3250,3530 3250,3250 3465,3035 3820,3035 3890,3105 U10.5
  Bottom Layer w15: LED5.1 3050,3821.19 U6.2
10M_EN: U10.2 U12.10
10S1: LED2.1 U8.7 U11.3 | length 955.6
  Top Layer w15: LED2.1 5780,3616.7 5780,3280 5730,3230 U11.3
  Bottom Layer w15: U8.7 5575.01,3821.69 LED2.1
10S2: LED4.1 U8.1 U11.4 U15.12 | length 1706.5
  Top Layer w15: U8.1 4975.01,3909.99 5010,3875 5249.2,3875 LED4.1 5450.8,3860 5680,3860 5880,3660 5880,3177.18 5830,3127.18 U11.4
10S3: LED6.1 U8.2 U11.5 U15.13 | length 1539.7
  Bottom Layer w15: U8.2 5080.01,3965 5080.01,3771.7 LED6.1 5188.3,3870 5370,3870 5515,3725 5515,3645 5680,3480 5680,3338.79 5773.79,3245 5812.19,3245 5930,3127.18 U11.5
10S_EN: U11.2 U15.10
+5: R21.2 R23.2 R25.2 R28.2 U10.16 U11.16 U12.14 U15.14 U18.14 U19.16 U20.14 U21.1 U21.4 U23.3 U24.16 U25.14 | length 7916.6
  Bottom Layer w20: U21.4 U21.1 2483.74,1936.26 2440,1980 2440,2235 2388.72,2286.28 2338.52,2286.28 U23.3 2335,2410 2270,2475 1066.72,2475 1005,2536.72 1005,2820.35 1005,2825 905,2925 905,3135 1020,3250 1155,3250 U19.16 1325,3360 1410,3275 3520,3275 ; U10.16 3490,3305 3520,3275 ; U11.16 5530,3412.82 5392.19,3275 3520,3275
+D5V: U6.3 U6.4 U6.16 U7.3 U7.4 U7.16 U8.3 U8.4 U8.16 U9.3 U9.4 U9.16 U16.3 U16.4 U16.16 U17.3 U17.4 U17.16 U21.2 U21.3 U21.5 U21.6 | length 7886.1
  Bottom Layer w20: U16.16 900.01,4169.99 965,4105 1075,4105 ; U16.4 U16.3 1100.01,4079.99 1075,4105 ; U17.16 2090,4135 2060,4105 ; U17.4 U17.3 2290,4075 2260,4105 ; U6.16 2950,4125 2930,4105 ; U6.4 U6.3 3150,4080 3125,4105 ; U7.16 4125.01,4120.01 4110,4105 ; U7.4 U7.3 4325.01,4079.99 4300,4105 ; U8.16 4975.01,4125.01 4955,4105 ; U8.4 U8.3 5175.01,4084.99 5155,4105 ; 6140.54,4105.04 6155.01,4119.52 U9.16 ; U9.4 U9.3 6355,4064.22 6314.22,4105 5155,4105 ; 1075,4105 2060,4105 ; 2060,4105 2260,4105 ; 2260,4105 2930,4105 ; 2930,4105 3125,4105 ; 3125,4105 4110,4105 ; 4110,4105 4300,4105 ; 4300,4105 4955,4105 ; 4955,4105 5155,4105
GND: C1.1 C2.1 C3.1 C4.1 C5.1 C6.1 DC1.2 DC1.3 R1.2 R2.2 R3.2 R4.2 R5.2 R6.2 R7.1 R8.1 R9.1 R10.1 R11.1 R12.1 R13.1 R14.1 R15.2 R16.2 R17.1 R18.1 R19.1 R20.1 SW1.3 SW1.4 SW2.3 SW2.4 SW3.3 SW3.4 U1.2 U2.3 U2.5 U2.8 U3.3 U3.5 U3.8 U4.3 U4.5 U4.8 U5.3 U5.5 U5.8 U6.5 U6.8 U7.5 U7.8 U8.5 U8.8 U9.5 U9.8 U10.1 U10.8 U10.15 U11.1 U11.8 U11.15 U12.7 U13.3 U13.5 U13.8 U14.3 U14.5 U14.8 U15.7 U16.5 U16.8 U17.5 U17.8 U18.7 U19.1 U19.8 U20.7 U23.2 U24.8 U25.4 U25.6 U25.7 U26.2 U26.3 U26.5 U26.6
H_RES: U12.4 U19.7 U19.15
NetC1_2: C1.2 R22.1 U20.13
NetC2_2: C2.2 R24.1 U20.5
NetC3_2: C3.2 R26.1 U20.1
NetC4_2: C4.2 R27.1 U24.11 X1.2
NetC5_2: C5.2 R27.2 U24.10 X1.1
NetC6_2: C6.2 R29.1 U20.9
NetDC1_1: DC1.1 U1.1 U22.1 U22.4 | length 1471.7
  Bottom Layer w20: DC1.1 1043.8,2365 1335,2365 U1.1 1768.74,1931.26 U22.1 U22.4
NetLED1_2: LED1.2 R1.1 | length 459.2
  Bottom Layer w15: R1.1 3345.5,3476.69 LED1.2
NetLED2_2: LED2.2 R2.1 | length 643.7
  Top Layer w15: R2.1 5138.31,3550 5513.3,3550 LED2.2
NetLED3_2: LED3.2 R3.1 | length 326.7
  Bottom Layer w15: R3.1 3041.24,3477.94 3041.24,3516.24 3182.52,3657.52 3256.33,3657.52 LED3.2
NetLED4_2: LED4.2 R4.1 | length 263.5
  Bottom Layer w15: R4.1 5180,3482.95 5357.5,3660.45 LED4.2
NetLED5_2: LED5.2 R5.1 | length 219.2
  Bottom Layer w15: R5.1 2925,3596.19 LED5.2
NetLED6_2: LED6.2 R6.1 | length 648.4
  Bottom Layer w15: LED6.2 4985,3566.7 4985,3445 5060,3370 5188.31,3370 R6.1
NetLED7_2: LED7.2 R7.2 | length 202.4
  Bottom Layer w15: LED7.2 4720.21,3653.72 4750,3623.92 R7.2
NetLED8_2: LED8.2 R8.2 | length 213.7
  Bottom Layer w15: R8.2 6767.15,3533.84 LED8.2
NetLED9_2: LED9.2 R9.2 | length 283
  Top Layer w15: LED9.2 4459.34,3657.57 4487.43,3657.57 4631.26,3513.74 4631.26,3480.44 R9.2
NetLED10_2: LED10.2 R10.2 | length 230.5
  Top Layer w15: LED10.2 6595,3568.85 R10.2
NetLED11_2: LED11.2 R11.2 | length 420.4
  Top Layer w15: LED11.2 4333.3,3666.7 4339.99,3660.01 4520,3480 R11.2
NetLED12_2: LED12.2 R12.2 | length 331.6
  Top Layer w15: LED12.2 6289.99,3666.7 R12.2
NetLED13_2: LED13.2 R13.2 | length 573.5
  Top Layer w15: LED13.2 4018.3,3666.7 4100,3585 4296.69,3585 R13.2
NetLED14_2: LED14.2 R14.2 | length 486.6
  Top Layer w15: LED14.2 6068.85,3555 6286.69,3555 R14.2
NetLED15_2: LED15.2 R15.1 | length 348.7
  Bottom Layer w15: R15.1 1199.99,3476.69 LED15.2
NetLED16_2: LED16.2 R16.1 | length 235.6
  Bottom Layer w15: R16.1 1005,3556.7 LED16.2
NetLED17_2: LED17.2 R17.2 | length 192.2
  Bottom Layer w15: R17.2 2577.61,3479.3 2577.61,3664.1 LED17.2
NetLED18_2: LED18.2 R18.2 | length 254.8
  Top Layer w15: LED18.2 2452.36,3517.89 2452.36,3484.37 R18.2
NetLED19_2: LED19.2 R19.2 | length 391.3
  Top Layer w15: LED19.2 2149.47,3666.7 R19.2
NetLED20_2: LED20.2 R20.2 | length 547.4
  Top Layer w15: LED20.2 1871.92,3545 2150.62,3545 R20.2
NetR21_1: R21.1 R22.2 SW1.1 SW1.2
NetR23_1: R23.1 R24.2 SW2.1 SW2.2
NetR25_1: R25.1 R26.2 SW3.1 SW3.2
NetR28_1: R28.1 R29.2 U26.1 U26.4
NetR30_1: R30.1 U6.13 | length 656.5
  Bottom Layer w15: R30.1 3025,4668.31 3025,4495 U6.13
NetR30_2: R30.2 U2.7 | length 493.9
  Bottom Layer w15: R30.2 3499.51,4785 U2.7
NetR31_1: R31.1 U6.12 | length 706
  Top Layer w15: R31.1 3000,4578.31 3000,4410 3075,4335 3285,4335 U6.12
NetR31_2: R31.2 U2.6 | length 641.6
  Bottom Layer w15: R31.2 3484.51,4670 U2.6
NetR32_1: R32.1 U6.11 | length 1016.2
  Bottom Layer w15: R32.1 3095,4828.31 3095,4545 3290,4350 3370,4350 U6.11
NetR32_2: R32.2 U2.4 | length 731.7
  Top Layer w15: R32.2 3723.03,4613.66 U2.4
NetR33_1: R33.1 U6.10 | length 1077.4
  Top Layer w15: R33.1 3075,4733.31 3075,4435 3135,4375 3445,4375 U6.10
NetR33_2: R33.2 U2.2 | length 533.9
  Top Layer w15: R33.2 3523.03,4698.66 U2.2
NetR34_1: R34.1 U6.9 | length 429.2
  Top Layer w15: U6.9 3825,4095 R34.1
NetR34_2: R34.2 U2.1 | length 452.8
  Bottom Layer w15: U2.1 3497.55,4375 3760,4375 3796.26,4338.74 3802.09,4338.74 3814.14,4326.69 R34.2
NetR35_1: R35.1 U6.15 | length 229.9
  Bottom Layer w15: R35.1 2914.45,4437.58 2914.45,4405.55 U6.15
NetR35_2: R35.2 U2.9 | length 1018.2
  Bottom Layer w15: R35.2 3175,4590.4 3175,4985 3260,5070 3470,5070 3523.03,5016.97 U2.9
NetR36_1: R36.1 U6.14 | length 389.9
  Bottom Layer w15: R36.1 2970,4497.63 2970,4445 3144.99,4270.01 U6.14
NetR36_2: R36.2 U2.10 | length 645
  Bottom Layer w15: R36.2 3220,4661.01 3220,4920 3260,4960 3374.51,4960 U2.10
NetR37_1: R37.1 U7.13 | length 707.7
  Top Layer w15: U7.13 4425,4275 4680,4530 4680,4620 4835.45,4775.45 4836.28,4775.45 4850.83,4790 R37.1
NetR37_2: R37.2 U3.7 | length 301
  Bottom Layer w15: U3.7 4440.63,4816.98 4440.63,4797.67 R37.2
NetR38_1: R38.1 U7.12 | length 778.4
  Bottom Layer w15: U7.12 4675,4419.99 4675,4725 4855,4905 R38.1
NetR38_2: R38.2 U3.6 | length 144.6
  Bottom Layer w15: U3.6 4349.09,5006.37 4448.31,4907.15 R38.2
NetR39_1: R39.1 U7.11 | length 503
  Bottom Layer w15: U7.11 4735,4379.99 4735,4548.31 R39.1
NetR39_2: R39.2 U3.4 | length 314.9
  Bottom Layer w15: U3.4 4250.49,4450.92 4250.49,4488.92 4428.89,4667.32 4440.63,4667.32 R39.2
NetR40_1: R40.1 U7.10 | length 349.5
  Bottom Layer w15: U7.10 4730.01,4270.01 4800,4340 4800,4498.31 R40.1
NetR40_2: R40.2 U3.2 | length 447.7
  Top Layer w15: U3.2 4049.09,4454.09 4150,4555 4443.31,4555 R40.2
NetR41_1: R41.1 U7.9 | length 190.2
  Bottom Layer w15: U7.9 4825,4273 4861.69,4309.69 R41.1
NetR41_2: R41.2 U3.1 | length 567.4
  Bottom Layer w15: U3.1 4033.61,4365 4368.31,4365 R41.2
NetR42_1: R42.1 U7.15 | length 537.1
  Top Layer w15: R42.1 3945,4040 4050,4145 4160,4145 4225,4210 U7.15
NetR42_2: R42.2 U3.9 | length 774.7
  Bottom Layer w15: R42.2 3885,4386.69 3885,4844.43 U3.9
NetR43_1: R43.1 U7.14 | length 1033.8
  Bottom Layer w15: U7.14 4410.01,4355 4515,4355 4610,4450 4610,4768.31 R43.1
NetR43_2: R43.2 U3.10 | length 549.5
  Bottom Layer w15: U3.10 4015.57,5075 4393.31,5075 R43.2
NetR44_1: R44.1 U8.13 | length 662.4
  Top Layer w15: R44.1 5025.49,4712.81 5025.49,4519.52 U8.13
NetR44_2: R44.2 U4.7 | length 487.2
  Bottom Layer w15: R44.2 5540.5,4795 U4.7
NetR45_1: R45.1 U8.12 | length 657
  Bottom Layer w15: R45.1 5055,4563.31 5055,4465 5185,4335 5310.01,4335 U8.12
NetR45_2: R45.2 U4.6 | length 636.9
  Bottom Layer w15: R45.2 5520.5,4675 U4.6
NetR46_1: R46.1 U8.11 | length 1007.5
  Bottom Layer w15: R46.1 5050,4918.31 5050,4640 5320,4370 5375.01,4370 U8.11
NetR46_2: R46.2 U4.4 | length 739.5
  Top Layer w15: R46.2 5356.69,5014.14 5371.24,4999.59 5371.24,4998.76 5755,4615 U4.4
NetR47_1: R47.1 U8.10 | length 1039.3
  Top Layer w15: R47.1 5075,4778.31 5075,4545 5275,4345 5510,4345 5575,4280 U8.10
NetR47_2: R47.2 U4.2 | length 541.6
  Top Layer w15: R47.2 5555,4711.69 U4.2
NetR48_1: R48.1 U8.9 | length 437.5
  Top Layer w15: U8.9 5870,4075.01 R48.1
NetR48_2: R48.2 U4.1 | length 475.4
  Bottom Layer w15: U4.1 5455,4439.64 5467.65,4427 5467.65,4422.35 5540,4350 5841.15,4350 5864.46,4326.69 R48.2
NetR49_1: R49.1 U8.15 | length 229.5
  Bottom Layer w15: R49.1 4950.06,4438.25 4950.06,4394.94 5015,4330 U8.15
NetR49_2: R49.2 U4.9 | length 1056.2
  Bottom Layer w15: R49.2 5170,4631.69 5170,4960 5290,5080 5484.5,5080 U4.9
NetR50_1: R50.1 U8.14 | length 386.8
  Bottom Layer w15: R50.1 5010,4494.14 5010,4435.01 U8.14
NetR50_2: R50.2 U4.10 | length 661.5
  Bottom Layer w15: R50.2 5220,4697.52 5220,4875 5315,4970 5415.5,4970 U4.10
NetR51_1: R51.1 U9.13 | length 702.9
  Top Layer w15: U9.13 6455,4282.97 6680,4507.97 6680,4573.31 R51.1
NetR51_2: R51.2 U5.7 | length 305.8
  Bottom Layer w15: U5.7 6275,5003.9 6483.31,4795.6 R51.2
NetR52_1: R52.1 U9.12 | length 781.3
  Bottom Layer w15: U9.12 6720,4434.99 6720,4750 6880,4910 R52.1
NetR52_2: R52.2 U5.6 | length 140.2
  Bottom Layer w15: U5.6 6375,5008.9 6473.31,4910.6 R52.2
NetR53_1: R53.1 U9.11 | length 499.3
  Bottom Layer w15: U9.11 6765,4380.01 6765,4551.64 R53.1
NetR53_2: R53.2 U5.4 | length 346
  Bottom Layer w15: U5.4 6275,4545 6403.33,4673.33 R53.2
NetR54_1: R54.1 U9.10 | length 341.2
  Bottom Layer w15: U9.10 6810,4325.01 6810,4479.98 R54.1
NetR54_2: R54.2 U5.2 | length 442.3
  Top Layer w15: U5.2 6181.17,4556.67 R54.2
NetR55_1: R55.1 U9.9 | length 183.1
  Bottom Layer w15: U9.9 6855.01,4400.88 6886.69,4432.56 R55.1
NetR55_2: R55.2 U5.1 | length 573.1
  Bottom Layer w15: U5.1 6070.5,4355 6380,4355 6465,4440 R55.2
NetR56_1: R56.1 U9.15 | length 524.2
  Top Layer w15: R56.1 5985,4035 6110,4160 6205,4160 6255.01,4210.01 U9.15
NetR56_2: R56.2 U5.9 | length 776.7
  Bottom Layer w15: R56.2 5916.69,4395 5916.69,4851.19 U5.9
NetR57_1: R57.1 U9.14 | length 1048.5
  Bottom Layer w15: U9.14 6429.99,4345 6555,4345 6555.86,4344.14 6665,4453.28 6665,4801.64 R57.1
NetR57_2: R57.2 U5.10 | length 551
  Bottom Layer w15: U5.10 6045.5,5080 6416.64,5080 R57.2
NetR58_1: R58.1 U16.13 | length 652.4
  Bottom Layer w15: R58.1 985,4668.31 985,4485.01 U16.13
NetR58_2: R58.2 U13.7 | length 496.7
  Bottom Layer w15: R58.2 1465.94,4785 U13.7
NetR59_1: R59.1 U16.12 | length 687.2
  Top Layer w15: R59.1 940,4598.31 940,4445 1040,4345 1225.01,4345 U16.12
NetR59_2: R59.2 U13.6 | length 644.3
  Bottom Layer w15: R59.2 1450.94,4670 U13.6
NetR60_1: R60.1 U16.11 | length 1020.9
  Bottom Layer w15: R60.1 1065,4818.31 1065,4510 1210,4365 1305.01,4365 U16.11
NetR60_2: R60.2 U13.4 | length 735.9
  Top Layer w15: R60.2 1686.86,4609.83 U13.4
NetR61_1: R61.1 U16.10 | length 976.6
  Top Layer w15: R61.1 1065,4703.31 1065,4560 1270,4355 1415.01,4355 U16.10
NetR61_2: R61.2 U13.2 | length 538.1
  Top Layer w15: R61.2 1281.69,4889.14 1296.24,4874.59 1296.24,4873.76 1486.86,4683.14 U13.2
NetR62_1: R62.1 U16.9 | length 437.5
  Top Layer w15: U16.9 1795,4075.01 R62.1
NetR62_2: R62.2 U13.1 | length 462.8
  Bottom Layer w15: U13.1 1468.78,4365 1764.94,4365 1795,4334.94 R62.2
NetR63_1: R63.1 U16.15 | length 226.6
  Bottom Layer w15: R63.1 867.06,4436.25 867.06,4402.95 U16.15
NetR63_2: R63.2 U13.9 | length 1022.7
  Bottom Layer w15: R63.2 1140,4576.69 1140,4985 1240,5085 1407.78,5085 U13.9
NetR64_1: R64.1 U16.14 | length 383
  Bottom Layer w15: R64.1 940,4478.31 940,4430.01 U16.14
NetR64_2: R64.2 U13.10 | length 633.4
  Bottom Layer w15: R64.2 1190,4641.69 1190,4920 1230,4960 1340.94,4960 U13.10
NetR65_1: R65.1 U17.13 | length 686.9
  Top Layer w15: U17.13 2640,4520.02 2640,4587.97 2826.69,4774.66 R65.1
NetR65_2: R65.2 U14.7 | length 312.9
  Bottom Layer w15: U14.7 2218.55,5000.29 2218.55,4970.75 R65.2
NetR66_1: R66.1 U17.12 | length 762.5
  Bottom Layer w15: U17.12 2600,4380 2600,4666.31 R66.1
NetR66_2: R66.2 U14.6 | length 154.5
  Bottom Layer w15: U14.6 2312.92,4999.65 2413.31,4899.27 R66.2
NetR67_1: R67.1 U17.11 | length 487.1
  Bottom Layer w15: U17.11 2670,4350 2670,4502.31 R67.1
NetR67_2: R67.2 U14.4 | length 306.4
  Bottom Layer w15: U14.4 2217.82,4451.82 2217.82,4482.82 2386.32,4651.32 2405.63,4651.32 R67.2
NetR68_1: R68.1 U17.10 | length 328.6
  Bottom Layer w15: U17.10 2755,4335 2755,4470.31 R68.1
NetR68_2: R68.2 U14.2 | length 439.8
  Top Layer w15: U14.2 2108,4542 R68.2
NetR69_1: R69.1 U17.9 | length 170.2
  Bottom Layer w15: U17.9 2789.99,4272.97 2826.69,4309.67 R69.1
NetR69_2: R69.2 U14.1 | length 542.6
  Bottom Layer w15: U14.1 1974.84,4385 2362.45,4385 2402.45,4425 R69.2
NetR70_1: R70.1 U17.15 | length 522.5
  Top Layer w15: R70.1 1910,4075 2015,4180 2099.98,4180 U17.15
NetR70_2: R70.2 U14.9 | length 771.6
  Bottom Layer w15: R70.2 1850,4386.69 1850,4843 U14.9
NetR71_1: R71.1 U17.14 | length 1030.7
  Bottom Layer w15: U17.14 2360,4340 2460,4340 2515,4395 2515,4715 2797.95,4997.95 2803.78,4997.95 2815.83,5010 R71.1
NetR71_2: R71.2 U14.10 | length 551.8
  Bottom Layer w15: U14.10 1977,5070 2353.31,5070 R71.2
NetU15_1: U15.1 U25.1
NetU15_2: U15.2 U18.1 U18.8 U18.12 U20.8
NetU18_2: U18.2 U20.12
NetU18_9: U18.9 U20.2
NetU18_10: U18.10
NetU18_13: U18.13 U20.6
NetU22_2: U22.2 U22.3 U22.5 U22.6 U23.1
NetU24_3: U24.3 U25.3
NetU25_2: U25.2 U25.5
pads on no net: U6.6 U8.6 U10.6 U11.6 U15.4 U15.5 U15.6 U16.2 U16.6 U18.4 U18.5 U18.6 U19.5 U19.6 U20.3 U20.4 U20.10 U20.11 U24.1 U24.2 U24.4 U24.5 U24.6 U24.7 U24.9 U24.12 U24.13 U24.14 U24.15 U25.8 U25.9 U25.10 U25.11 U25.12 U25.13

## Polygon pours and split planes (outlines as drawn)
NetU22_2 on Bottom Layer "NONET_L-01_P-001" (solid, pour order 2): 2090,2340 2090,1990 2360,1990 2360,2120 2205,2120 2165,2160 2165,2340
10H2 on Bottom Layer "NONET_L02_P001" (solid, shelved, pour order 1): 830,1805 6925,1805 6925,5165 830,5165
GND on Bottom Layer "NONET_L02_P000" (solid, shelved, pour order 0): 830,1805 6925,1805 6925,5165 830,5165

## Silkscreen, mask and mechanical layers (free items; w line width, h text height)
Mechanical 15:
  lines w10: 835,4390 6920,4390 6920,5075 835,5075 835,4390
